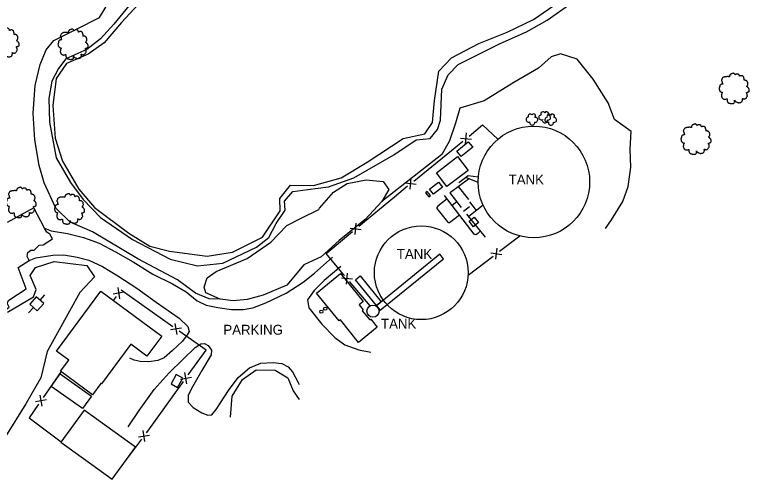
# Model space of a CAD drawing. Extents: x 2160437 to 2172832, y 205694 to 212444.
# Drawn here: x 2172011.7 to 2172382.8, y 206137.2 to 206371.7 of the extents above; entities that cross this region are included whole.
import ezdxf

# ---------------------------------------------------------------- set-up
doc = ezdxf.new("R2010")
doc.units = 0
for name, color, linetype in [('Default', 7, 'Continuous'), ('RD_EX_Bldg', 7, 'Continuous'), ('RD_EX_BldgApp', 7, 'Continuous'), ('RD_EX_BldgApp_txCode', 7, 'Continuous'), ('RD_EX_DR_Pipe', 7, 'Continuous'), ('RD_EX_Fence_Other', 7, 'Continuous'), ('RD_EX_H2O', 7, 'Continuous'), ('RD_EX_Misc', 7, 'Continuous'), ('RD_EX_Parking_Paved', 7, 'Continuous'), ('RD_EX_Parking_Unpaved', 7, 'Continuous'), ('RD_EX_Road_txCode', 7, 'Continuous'), ('RD_EX_UT', 7, 'Continuous'), ('RD_EX_VEG', 7, 'Continuous'), ('RD_EX_VEG_ShrubLine', 7, 'Continuous'), ('RD_EX_VEG_TreeLine', 7, 'Continuous')]:
    doc.layers.add(name, color=color, linetype=linetype)

# ---------------------------------------------------------------- blocks, each defined once
blk = doc.blocks.new('RD_EX_Fnce_Other')
at = {"layer": 'Default'}
for points in [[(-0.0417, -0.0417), (0.0417, 0.0417)], [(-0.0417, 0.0417), (0.0417, -0.0417)]]:
    blk.add_lwpolyline(points, dxfattribs=at)
blk = doc.blocks.new('T2')
at = {"layer": 'RD_EX_VEG'}
for points in [[(0.05, 7.21), (-0.25, 7.24), (-0.57, 7.14), (-0.82, 7.04), (-1.05, 6.96), (-1.27, 6.86), (-1.57, 6.69), (-1.8, 6.49), (-1.92, 6.24), (-1.97, 6.01), (-2.02, 5.74), (-2.02, 5.56), (-2.15, 5.54), (-2.3, 5.56), (-2.55, 5.64), (-2.8, 5.64), (-3.05, 5.64), (-3.4, 5.61), (-3.75, 5.61), (-4.02, 5.56), (-4.35, 5.51), (-4.72, 5.39), (-5.07, 5.26), (-5.37, 5.01), (-5.62, 4.54), (-5.75, 4.19), (-5.9, 3.94), (-5.75, 3.49), (-5.57, 3.14), (-5.55, 2.94), (-5.47, 2.52), (-5.37, 2.29), (-5.25, 2.09), (-5.32, 2.07), (-5.7, 2.02), (-6, 1.92), (-6.42, 1.69), (-6.64, 1.47), (-6.74, 1.14), (-6.77, 0.79), (-6.87, 0.59), (-6.94, 0.32), (-6.97, 0.24), (-7.02, -0.08), (-6.92, -0.53), (-6.89, -0.88), (-6.77, -1.11), (-6.62, -1.28), (-6.44, -1.53), (-6.05, -1.76), (-5.72, -1.86), (-5.52, -1.88), (-5.7, -2.38), (-5.75, -2.73), (-5.87, -3.13), (-5.87, -3.21), (-5.92, -3.68), (-5.77, -4.01), (-5.7, -4.38), (-5.52, -4.61), (-5.25, -4.91), (-4.92, -5.13), (-4.42, -5.26), (-4.02, -5.23), (-3.45, -5.06), (-3.2, -4.98), (-3.22, -5.16), (-3.2, -5.53), (-3.2, -5.96), (-3.05, -6.28), (-2.95, -6.56), (-2.8, -6.81), (-2.47, -7.03), (-2.07, -7.11), (-1.65, -7.26), (-1.2, -7.33), (-0.7, -7.36), (-0.1, -7.21), (0.18, -7.08), (0.28, -6.91), (0.48, -6.53), (0.43, -6.31), (0.45, -5.71), (0.55, -5.88), (0.73, -6.23), (1.23, -6.53), (1.63, -6.71), (2.1, -6.86), (2.4, -6.93), (2.88, -6.86), (3.25, -6.78), (3.63, -6.66), (3.93, -6.38), (4.1, -6.11), (4.15, -5.83), (4.23, -5.46), (4.28, -5.28)], [(4.28, -5.28), (4.2, -5.11), (4.15, -4.86), (4.23, -4.88), (4.4, -4.93), (4.68, -5.06), (4.9, -5.13), (5.23, -5.11), (5.5, -5.01), (5.95, -4.73), (6.22, -4.26), (6.5, -3.86), (6.57, -3.53), (6.52, -3.31), (6.5, -2.81), (6.3, -2.56), (6.25, -2.43), (6.15, -2.03), (6.22, -1.98), (6.5, -1.93), (6.87, -1.81), (7.15, -1.68), (7.37, -1.51), (7.45, -1.28), (7.42, -0.88), (7.47, -0.48), (7.4, -0.33), (7.3, -0.18), (7.22, 0.02), (7.07, 0.17), (6.97, 0.32), (6.87, 0.42), (6.75, 0.57), (6.57, 0.69), (6.42, 0.74), (6.37, 0.89), (6.52, 1.09), (6.57, 1.19), (6.6, 1.42), (6.82, 1.77), (6.87, 2.17), (6.82, 2.59), (6.77, 2.87), (6.62, 3.14), (6.42, 3.39), (6.3, 3.56), (6.12, 3.69), (5.8, 3.81), (5.55, 3.86), (5.2, 3.86), (5, 3.91), (5.03, 3.96), (5.03, 4.11), (5.03, 4.39), (4.95, 4.84), (4.8, 5.34), (4.8, 5.36), (4.7, 5.61), (4.48, 5.81), (4.3, 5.91), (4.1, 6.04), (3.85, 6.06), (3.55, 6.06), (3.28, 6.01), (3.08, 5.91), (2.9, 5.79), (2.83, 5.94), (2.73, 6.24), (2.68, 6.39), (2.53, 6.56), (2.3, 6.76), (1.85, 6.89), (1.23, 6.81), (0.93, 6.61), (0.78, 6.44), (0.73, 6.56), (0.53, 6.76), (0.43, 6.94), (0.25, 7.06), (0.1, 7.16), (0, 7.21)]]:
    blk.add_spline(points, degree=3, dxfattribs=at)
blk = doc.blocks.new('PP')
at = {"layer": 'RD_EX_UT'}
for p, q in [((2.49, 2.51), (-2.51, 2.51)), ((-2.51, 2.51), (-2.51, -2.49)), ((2.49, -2.49), (2.49, 2.51)), ((-5.94, -0.05), (-2.47, -0.05)), ((-2.51, -2.49), (2.49, -2.49)), ((2.42, -0.05), (6.06, -0.05))]:
    blk.add_line(p, q, dxfattribs=at)

msp = doc.modelspace()

# ---------------------------------------------------------------- linework, layer by layer
at = {"layer": 'RD_EX_Bldg'}
for points in [[(2172224.7, 206291.95), (2172235.43, 206300.08), (2172240.76, 206293.05), (2172230.02, 206284.92)], [(2172175.55, 206217.19), (2172164.18, 206231.21), (2172176.27, 206241), (2172187.73, 206226.86), (2172185.72, 206225.23), (2172187.78, 206222.69), (2172187.29, 206222.29), (2172191.06, 206217.63), (2172191.53, 206218.02), (2172194.85, 206213.93), (2172185.45, 206206.3), (2172176.2, 206217.71)], [(2172055.24, 206232.08), (2172086, 206209.39), (2172078.53, 206199.28), (2172070.32, 206205.33), (2172055.57, 206185.33), (2172055.25, 206185.56), (2172051.07, 206179.88), (2172034.92, 206191.79), (2172039.01, 206197.33), (2172032.92, 206201.83)], [(2172034.68, 206190.44), (2172050.45, 206179.2), (2172045.91, 206172.83), (2172030.14, 206184.08)], [(2172093.27, 206190.07), (2172090.67, 206185.38), (2172093.98, 206183.54), (2172096.59, 206188.23)], [(2172035.06, 206155.87), (2172061.03, 206137.16), (2172072.71, 206153.36), (2172046.74, 206172.08)]]:
    msp.add_lwpolyline(points, close=True, dxfattribs=at)
at = {"layer": 'RD_EX_BldgApp'}
for points in [[(2172235.06, 206302.84), (2172240.82, 206307.6), (2172243.04, 206304.92), (2172237.29, 206300.15)], [(2172196.3, 206222.47), (2172228.36, 206248.54), (2172226.47, 206250.88), (2172194.4, 206224.8)], [(2172196.9, 206226.83), (2172194.44, 206224.83), (2172183.78, 206237.95), (2172186.24, 206239.95)]]:
    msp.add_lwpolyline(points, close=True, dxfattribs=at)
for centre, radius in [((2172273.93, 206287.29), 28.18), ((2172217.07, 206241.44), 23.66), ((2172192.69, 206222.06), 3.08)]:
    msp.add_circle(centre, radius, dxfattribs=at)
at = {"layer": 'RD_EX_DR_Pipe'}
for points in [[(2172237.39, 206274.35), (2172231.71, 206281.76), (2172231.82, 206282.19), (2172240.89, 206288.83)], [(2172236.07, 206286.98), (2172240.76, 206290.47), (2172245.88, 206289.93)], [(2172245.75, 206287.07), (2172239.52, 206289.54)], [(2172235.68, 206285.02), (2172240.92, 206278.47)], [(2172247.02, 206262.53), (2172245.7, 206261.25), (2172244.99, 206260.75), (2172244.34, 206260.6), (2172243.84, 206260.96), (2172228.87, 206280.47)], [(2172230.14, 206278.82), (2172225.43, 206275.12), (2172224.96, 206274.43), (2172225, 206273.82), (2172230.35, 206267.1), (2172230.81, 206266.89), (2172231.27, 206266.86), (2172236.35, 206270.73)], [(2172232.68, 206275.51), (2172235.09, 206277.35)], [(2172244.95, 206272.93), (2172241.56, 206277.18)], [(2172238.41, 206272.54), (2172241.35, 206274.91)], [(2172248.3, 206275.59), (2172241.07, 206269.84)], [(2172249.57, 206259.4), (2172240.1, 206271.02)]]:
    msp.add_lwpolyline(points, dxfattribs=at)
at = {"layer": 'RD_EX_Fence_Other'}
for points in [[(2172241.22, 206310.47), (2172248.05, 206316.09), (2172255.79, 206308.85)], [(2172213.29, 206287.76), (2172232.35, 206303.17), (2172238.13, 206307.93)], [(2172185.48, 206264.89), (2172203.51, 206279.85), (2172210.17, 206285.25)], [(2172178.26, 206239.99), (2172177.77, 206240.57), (2172168.98, 206251.19), (2172182.4, 206262.34)], [(2172256.63, 206252.26), (2172266.85, 206260.01)], [(2172240.7, 206240.18), (2172253.45, 206249.85)], [(2172191.26, 206224.79), (2172180.86, 206236.95)], [(2172091.6, 206214.18), (2172065.42, 206232.59)], [(2172063.04, 206229.53), (2172061.52, 206227.44)], [(2172099.36, 206189.83), (2172108.41, 206202.36), (2172094.87, 206211.88)], [(2172035.22, 206191.57), (2172026.09, 206178.43)], [(2172078.28, 206160.64), (2172078.89, 206161.46), (2172097.02, 206186.58)], [(2172023.81, 206175.15), (2172019, 206168.23), (2172035.19, 206156.05)], [(2172066.37, 206144.58), (2172075.9, 206157.43)]]:
    msp.add_lwpolyline(points, dxfattribs=at)
at = {"layer": 'RD_EX_H2O'}
msp.add_lwpolyline([(2172074.2, 206377.11), (2172065.69, 206367.73), (2172056.91, 206357.52), (2172048.91, 206351.83), (2172037.95, 206347.06), (2172032.74, 206339.57), (2172030.96, 206325.86), (2172032.13, 206309.33), (2172035.92, 206297.85), (2172044.08, 206283.64), (2172052.07, 206274.39), (2172069.3, 206261.47), (2172079.95, 206254.82), (2172089.88, 206252.42), (2172108.93, 206249.8), (2172121.77, 206251.91), (2172136.86, 206259.46), (2172145.75, 206272.7), (2172145.6, 206278.91), (2172151.01, 206285.67), (2172162.72, 206285.54), (2172176.65, 206289.38), (2172189.79, 206297.29), (2172207.92, 206309.19), (2172218.85, 206311.53), (2172222.83, 206317.25), (2172223.84, 206328.34), (2172225.97, 206343.27), (2172232.29, 206349.94), (2172246.23, 206357.27), (2172260.53, 206362.85), (2172273.76, 206369.34), (2172286.27, 206377.96)], dxfattribs=at)
at = {"layer": 'RD_EX_Misc'}
for points in [[(2172221.28, 206283.63), (2172225.83, 206287.16), (2172227.74, 206284.7), (2172223.19, 206281.17)], [(2172221.73, 206280.41), (2172219.98, 206282.51), (2172219.17, 206281.83), (2172220.92, 206279.74)], [(2172243.48, 206264.69), (2172241.27, 206267.42), (2172243.82, 206269.48), (2172246.03, 206266.75)]]:
    msp.add_lwpolyline(points, close=True, dxfattribs=at)
for centre, radius in [((2172168.57, 206223.27), 0.796), ((2172166.59, 206221.75), 0.794)]:
    msp.add_circle(centre, radius, dxfattribs=at)
at = {"layer": 'RD_EX_Parking_Paved'}
msp.add_lwpolyline([(2171980.74, 206204.65), (2171992.05, 206211.74), (2172008.92, 206224.14), (2172007.94, 206226.1), (2172008.79, 206227.54), (2172017.45, 206233.35), (2172013.54, 206244.08), (2172019.01, 206247.66), (2172018.01, 206249.68), (2172018.37, 206251.59), (2172019.95, 206252.84), (2172021.51, 206252.84), (2172024.02, 206255.34), (2172026.11, 206255.5), (2172030.82, 206258.52), (2172029.45, 206260.96), (2172027.87, 206261.93), (2172026.71, 206263.93), (2172021.33, 206274.21), (2172007.96, 206266.84), (2172007.44, 206267.03), (2172007.16, 206267.51), (2171998.23, 206284.13), (2171993.96, 206281.68)], dxfattribs=at)
at = {"layer": 'RD_EX_Parking_Unpaved'}
for points in [[(2172026.71, 206263.93), (2172030.15, 206262.63), (2172038.39, 206261.18), (2172046.42, 206259.25), (2172054.47, 206256.44), (2172062.7, 206252.06), (2172071.54, 206247.01), (2172081.51, 206240.8), (2172091.4, 206235.8), (2172098.36, 206231.87), (2172103.87, 206227.27), (2172108.51, 206225.16), (2172114.32, 206223.89), (2172121.2, 206222.94), (2172127.09, 206222.85), (2172132.06, 206223.75), (2172138.65, 206226.29), (2172148.8, 206231.08), (2172157.44, 206236.72), (2172163.13, 206241.26), (2172172.25, 206249.35)], [(2172019.01, 206247.66), (2172022.32, 206248.94), (2172030.92, 206250.38), (2172036.61, 206250.41), (2172043.31, 206249.35), (2172049.18, 206247.8), (2172055.99, 206244.6), (2172063.89, 206239.89), (2172073.45, 206233.63), (2172083.17, 206226.59), (2172094.79, 206218.52), (2172099.25, 206214.27), (2172099.77, 206211.75), (2172098.83, 206210.08), (2172096.41, 206206.92), (2172091.48, 206202.14), (2172087.24, 206198.53), (2172083.94, 206197.11), (2172079.41, 206196.47), (2172075.12, 206196.59), (2172071.98, 206197.38), (2172069.81, 206198.37)], [(2172176.5, 206244.61), (2172168.06, 206237.53), (2172162.97, 206232.56), (2172159.68, 206227.72), (2172160.32, 206223.77), (2172166.87, 206215.49), (2172173.42, 206208.75), (2172178.45, 206205.08), (2172185.53, 206202.53), (2172191.63, 206201.42)], [(2172069, 206163.68), (2172074.51, 206171.83), (2172082.09, 206182.42), (2172089.82, 206190.86), (2172096.61, 206197.68), (2172102.87, 206203.64), (2172105.74, 206205.59), (2172107.52, 206205.76), (2172109.47, 206204.69), (2172111.06, 206202.37), (2172110.98, 206200.03), (2172106.16, 206192.07), (2172100.89, 206182.62), (2172099.4, 206179.4), (2172099.3, 206176.11), (2172101.94, 206173.45), (2172106.19, 206170.75), (2172109.24, 206169.52), (2172111.21, 206169.71), (2172113.44, 206172.4), (2172119.7, 206182.04), (2172124.53, 206188.51), (2172130.29, 206193.49), (2172136.1, 206195.73), (2172142.34, 206196.2), (2172146.63, 206195.68), (2172149.89, 206193.93), (2172152.03, 206191.48), (2172154.94, 206186.1), (2172155.39, 206185.05)]]:
    msp.add_lwpolyline(points, dxfattribs=at)
at = {"layer": 'RD_EX_VEG'}
for centre, radius, start, end in [((2172272.12, 206320.5), 1.08, 34.9763, 204.756), ((2172273.89, 206320.65), 0.995, 308.7626, 152.0467), ((2172277.71, 206319.89), 1.26, 96.4518, 294.734), ((2172278.55, 206321.6), 1.08, 34.9763, 204.756), ((2172280.32, 206321.75), 0.995, 308.7626, 152.0467), ((2172281.62, 206320.41), 1.08, 34.9763, 204.756), ((2172281.11, 206319.77), 1.22, 256.5667, 98.1046), ((2172283.39, 206320.56), 0.995, 308.7626, 152.0467), ((2172271.28, 206318.79), 1.26, 96.4518, 294.734), ((2172273.09, 206317.35), 1.32, 166.8827, 5.7589), ((2172274.68, 206318.67), 1.22, 256.5667, 98.1046), ((2172279.52, 206318.45), 1.32, 166.8827, 5.7589), ((2172280.78, 206318.7), 1.26, 96.4518, 294.734), ((2172282.59, 206317.26), 1.32, 166.8827, 5.7589), ((2172284.18, 206318.58), 1.22, 256.5667, 98.1046)]:
    msp.add_arc(centre, radius, start, end, dxfattribs=at)
at = {"layer": 'RD_EX_VEG_ShrubLine'}
for points in [[(2172115.45, 206228.11), (2172110, 206228.26), (2172103.03, 206231.11), (2172094.02, 206237.86), (2172073.94, 206248.48), (2172051.07, 206262.06), (2172039.71, 206266.91), (2172032.49, 206274.11), (2172026.53, 206286.89), (2172024.01, 206295.57), (2172021.94, 206308.49), (2172021.1, 206322.02), (2172022.14, 206335.96), (2172024.51, 206346.54), (2172027.69, 206354), (2172031.45, 206358.76), (2172042.94, 206364.45), (2172054.51, 206370.31), (2172059.28, 206378)], [(2172069.33, 206376.19), (2172061.82, 206366.89), (2172055.05, 206359.47), (2172048.08, 206354.16), (2172037.63, 206349.37), (2172033.79, 206344.65), (2172030.49, 206338.1), (2172028.9, 206329.49), (2172029.35, 206317.41), (2172032.64, 206299.49), (2172039.97, 206286.93), (2172046.37, 206278.4), (2172055.08, 206269.35), (2172071.19, 206258.19), (2172090.19, 206248.32), (2172104.06, 206244.89), (2172116.93, 206246.2), (2172133.88, 206254.33), (2172140.05, 206259.26), (2172143.8, 206266.35), (2172148.38, 206272.96), (2172148.02, 206277.62), (2172152.15, 206282.52), (2172159.81, 206283.5), (2172170.16, 206284.83), (2172183.04, 206289.36), (2172203.16, 206300.98), (2172214.55, 206308.53), (2172221.56, 206309.26), (2172225.28, 206313.71), (2172226.83, 206318.52), (2172227.38, 206334.17), (2172230.65, 206341.38), (2172235.64, 206346.53), (2172256.89, 206357.11), (2172270.19, 206363.04), (2172280.74, 206368.99), (2172292.61, 206377.37)], [(2172310.12, 206263.74), (2172313.11, 206268.21), (2172318.81, 206277.49), (2172321.51, 206285.06), (2172322.97, 206294.79), (2172322.51, 206303.79), (2172323.17, 206312.71), (2172314.74, 206318.88), (2172311.46, 206327.27), (2172303.87, 206339.16), (2172295.76, 206349.31), (2172287.46, 206352.02), (2172282.68, 206350.38), (2172276.33, 206344.79), (2172263.9, 206337.51), (2172248.91, 206328.32), (2172236.57, 206324.5), (2172234.3, 206316.95), (2172231.34, 206308.12), (2172227.41, 206301.11), (2172213.43, 206290.19), (2172197.23, 206277.41)]]:
    msp.add_lwpolyline(points, dxfattribs=at)
at = {"layer": 'RD_EX_VEG_TreeLine'}
msp.add_lwpolyline([(2172165.62, 206274.09), (2172172.66, 206282.12), (2172179.72, 206286.44), (2172189.19, 206288.39), (2172197.9, 206287.5), (2172200.77, 206283.54), (2172197.23, 206277.41), (2172188.76, 206268.33), (2172175.64, 206257.66), (2172166.43, 206249.55), (2172157.78, 206245.43), (2172149.09, 206235.18), (2172137.18, 206230.21), (2172129.18, 206228.01), (2172122.04, 206227.23), (2172115.45, 206228.11), (2172108.33, 206231.35), (2172107.5, 206234.17), (2172108.88, 206238.84), (2172113.55, 206242.12), (2172129.16, 206248.7), (2172141.16, 206256.91), (2172149.1, 206265.28), (2172156.05, 206268.9), (2172165.3, 206273.39)], close=True, dxfattribs=at)
for points in [[(2172008.12, 206221.53), (2172021.21, 206229.35), (2172022.64, 206232.95), (2172019.52, 206240.09), (2172022.22, 206244.16), (2172031.62, 206247.1), (2172048.1, 206245.11), (2172052.03, 206239.3), (2172044.63, 206231.43), (2172028.11, 206201.63), (2172024.88, 206188.47), (2172017.42, 206175.32), (2172007.14, 206158.8)], [(2172120.78, 206168.59), (2172121.52, 206179.07), (2172126.82, 206187.47), (2172133.65, 206192.42), (2172143.33, 206192.25), (2172149.61, 206188.34), (2172152.35, 206181.79), (2172155.45, 206177.41)]]:
    msp.add_lwpolyline(points, dxfattribs=at)

# ---------------------------------------------------------------- block references
at = {"layer": 'RD_EX_Fence_Other'}
for p, xscale, yscale, rotation in [((2172239.67, 206309.2), 48, 48, 39.43311), ((2172211.73, 206286.5), 48, 48, 38.960215), ((2172183.94, 206263.62), 48, 48, 39.693376), ((2172255.04, 206251.06), 48, 48, 37.162772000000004), ((2172179.56, 206238.47), 48.00000000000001, 47.99999999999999, 130.525123), ((2172064.22, 206231.15), 48.00000000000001, 47.99999999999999, -126.03336999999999), ((2172093.23, 206213.03), 48, 48, 144.880482), ((2172098.19, 206188.21), 48, 48, 54.178313), ((2172024.95, 206176.79), 47.99999999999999, 48.00000000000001, -124.79628700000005), ((2172077.09, 206159.04), 48, 48, 53.45369900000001)]:
    msp.add_blockref('RD_EX_Fnce_Other', p, dxfattribs=dict(at, xscale=xscale, yscale=yscale, rotation=rotation))
at = {"layer": 'RD_EX_UT', "xscale": 1.0199999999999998, "yscale": 1.02, "rotation": -131.15721400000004}
msp.add_blockref('PP', (2172022.87, 206225.75), dxfattribs=at)
at = {"layer": 'RD_EX_VEG', "xscale": 1.0499999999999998, "yscale": 1.0499999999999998}
for p in [(2172006.13, 206357.68), (2172040.96, 206356.88), (2172374.88, 206334.54), (2172355.62, 206308.96), (2172014.79, 206276.99), (2172039.18, 206273.74)]:
    msp.add_blockref('T2', p, dxfattribs=at)

# ---------------------------------------------------------------- texts
at = {"layer": 'RD_EX_BldgApp_txCode'}
for p in [(2172261.23, 206286.01), (2172204.72, 206248.47), (2172196.75, 206213.2)]:
    msp.add_text('TANK', height=5, dxfattribs=at).set_placement(p)
at = {"layer": 'RD_EX_Road_txCode'}
msp.add_text('PARKING', height=5, dxfattribs=at).set_placement((2172117.11, 206210.16))

doc.saveas('drawing.dxf')
